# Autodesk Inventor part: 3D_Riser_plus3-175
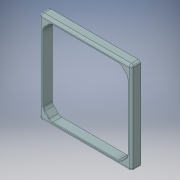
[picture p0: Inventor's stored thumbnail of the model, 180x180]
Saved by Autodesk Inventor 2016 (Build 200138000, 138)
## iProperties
Created: 2016-01
Part Number: 3D_Riser_plus3-175
Material: Generic
Document SubType Name: Modeling
Designer: John
Density: 1 g/cm^3
Appearance: Default
Author: John
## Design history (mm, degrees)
feature "Base1"
sketch "Sketch1"
  geometry: L1 (0, 0)-(180, 0) reference; L2 (185, 5)-(185, 185) reference; L3 (180, 190)-(0, 190) reference; L4 (-5, 185)-(-5, 5) reference; L5 (22.142, 182)-(157.858, 182) reference; L6 (174.071, 169.929)-(164.929, 179.071) reference; L7 (177, 162.858)-(177, 27.142) reference; L8 (164.929, 10.929)-(174.071, 20.071) reference; L9 (157.858, 8)-(22.142, 8) reference; L10 (5.929, 20.071)-(15.071, 10.929) reference; L11 (3, 27.142)-(3, 162.858) reference; L12 (15.071, 179.071)-(5.929, 169.929) reference; C1 r 1.75 at (3, 182) reference; C2 r 1.75 at (177, 8) reference; C3 r 1.75 at (177, 182) reference; C4 r 1.75 at (3, 8) reference; A1 r 5 centre (0, 5) between (-5, 5) and (0, 0) reference; A2 r 5 centre (180, 5) between (180, 0) and (185, 5) reference; A3 r 5 centre (180, 185) between (185, 185) and (180, 190) reference; A4 r 5 centre (0, 185) between (0, 190) and (-5, 185) reference; A5 r 10 centre (157.858, 172) between (164.929, 179.071) and (157.858, 182) reference; A6 r 10 centre (167, 162.858) between (177, 162.858) and (174.071, 169.929) reference; A7 r 10 centre (167, 27.142) between (174.071, 20.071) and (177, 27.142) reference; A8 r 10 centre (157.858, 18) between (157.858, 8) and (164.929, 10.929) reference; A9 r 10 centre (22.142, 18) between (15.071, 10.929) and (22.142, 8) reference; A10 r 10 centre (13, 27.142) between (3, 27.142) and (5.929, 20.071) reference; A11 r 10 centre (13, 162.858) between (5.929, 169.929) and (3, 162.858) reference; A12 r 10 centre (22.142, 172) between (22.142, 182) and (15.071, 179.071) reference; 1 further point
extrude "Extrusion1" join sketch "Sketch1" distance "d0" = 6.35; taper "d1" = 0 deg
body "Solid1"
node "Projected Loop1"
